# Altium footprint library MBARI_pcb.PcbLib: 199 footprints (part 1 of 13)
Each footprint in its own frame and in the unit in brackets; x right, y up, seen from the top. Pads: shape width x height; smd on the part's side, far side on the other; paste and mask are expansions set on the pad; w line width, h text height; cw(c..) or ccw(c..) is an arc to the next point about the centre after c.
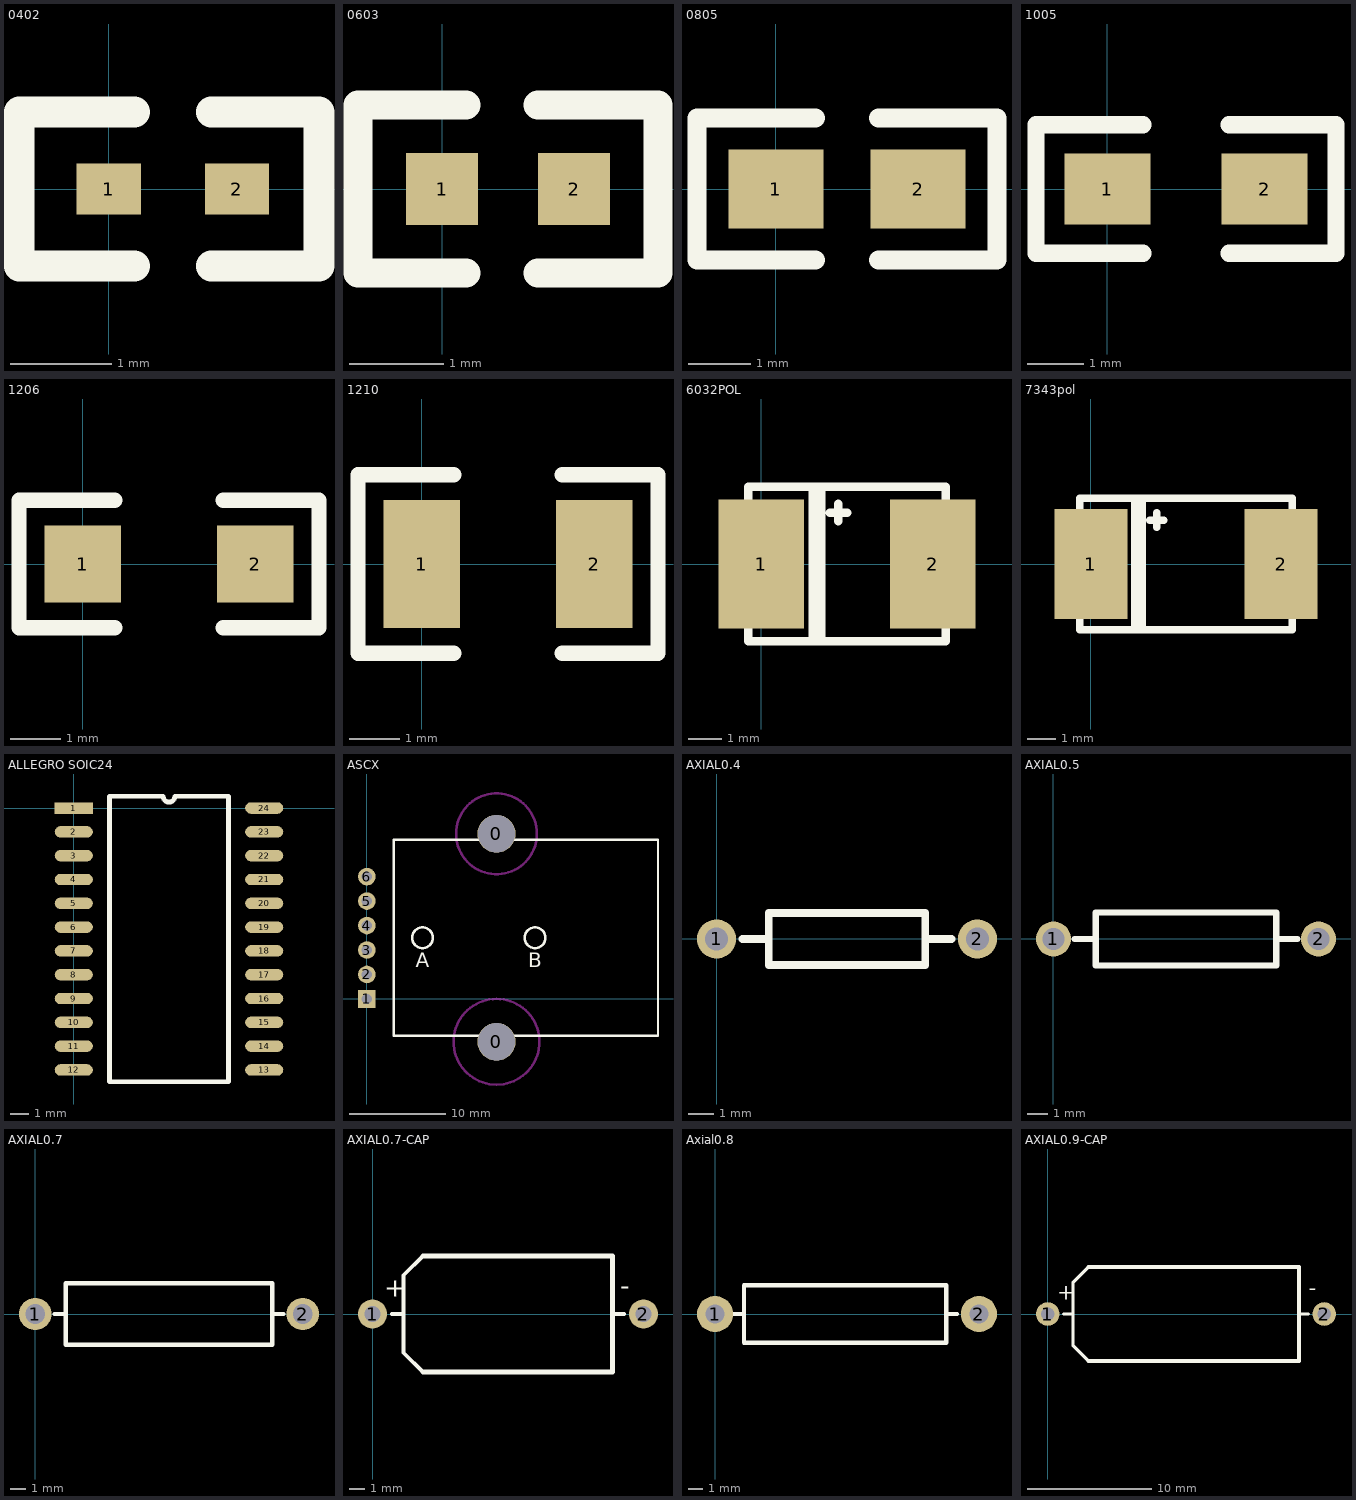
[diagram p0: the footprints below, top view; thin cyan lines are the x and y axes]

## 0402 [mil]
pads (2):
  rect 25x20 smd: 1(0,0) 2(50,0)
TopOverlay:
  lines w12: 10,-30 -35,-30 -35,30 10,30 ; 40,-30 82,-30 82,30 40,30

## 0603 [mil]
pads (2):
  rect 30x30 smd: 1(0,0) 2(55,0)
TopOverlay:
  lines w12: 10,-35 -35,-35 -35,35 10,35 ; 40,-35 90,-35 90,35 40,35

## 0805 [mil]
pads (2):
  rect 60x50 smd: 1(0,0) 2(90,0)
TopOverlay:
  lines w12: 25,-45 -50,-45 -50,45 25,45 ; 65,-45 140,-45 140,45 65,45

## 1005 [mil]
pads (2):
  rect 60x50 smd: 1(0,0) 2(110,0)
TopOverlay:
  lines w12: 25,-45 -50,-45 -50,45 25,45 ; 85,-45 160,-45 160,45 85,45

## 1206 [mil]
pads (2):
  rect 60x60 smd: 1(0,0) 2(135,0)
TopOverlay:
  lines w12: 25,-50 -50,-50 -50,50 25,50 ; 110,-50 185,-50 185,50 110,50

## 1210 [mil]
pads (2):
  rect 60x100 smd: 1(0,0) 2(135,0)
TopOverlay:
  lines w12: 25,-70 -50,-70 -50,70 25,70 ; 110,-70 185,-70 185,70 110,70

## 6032POL [mil]
pads (2):
  rect 100x150 smd: 1(0,0) 2(200,0)
TopOverlay:
  lines w10: -15,-75 -15,-90 215,-90 215,-75 ; -15,75 -15,90 215,90 215,75 ; 60,-90 60,90 ; 70,-90 70,90 ; 80,60 100,60 ; 90,50 90,70

## 7343pol [mil]
pads (2):
  rect 100x150 smd: 1(0,0) 2(260,0)
TopOverlay:
  lines w10: -15,-75 -15,-90 275,-90 275,-75 ; -15,75 -15,90 275,90 275,75 ; 60,-90 60,90 ; 70,-90 70,90 ; 80,60 100,60 ; 90,50 90,70

## ALLEGRO SOIC24 [mil]
pads (24):
  rect 80x24 smd: 1(0,0)
  oval 80x24 smd: 2(0,-50) 3(0,-100) 4(0,-150) 5(0,-200) 6(0,-250) 7(0,-300) 8(0,-350) 9(0,-400) 10(0,-450) 11(0,-500) 12(0,-550) 13(400,-550) 14(400,-500) 15(400,-450) 16(400,-400) 17(400,-350) 18(400,-300) 19(400,-250) 20(400,-200) 21(400,-150) 22(400,-100) 23(400,-50) 24(400,0)
TopOverlay:
  lines w10: 75,-575 75,25 187.5,25 ccw(c200,25) 212.5,25 325,25 325,-575 75,-575

## ASCX [mil]
pads (8):
  round 155 hole 152: 0(530,-175) 0(530,675)
  rect 72x72 hole 42: 1(0,0)
  round 72 hole 42: 2(0,100) 3(0,200) 4(0,300) 5(0,400) 6(0,500)
TopOverlay:
  circle w10: c227.57,250 r42.43
  circle w10: c687.57,250 r42.43
  lines w10: 110,-150 110,650 1190,650 1190,-150 110,-150
  text "A" at 200,130 h60
  text "B" at 660,130 h60
KeepOutLayer:
  circle w10: c530,675 r165.3
  circle w10: c530,-175 r175.29

## AXIAL0.4 [mil]
pads (2):
  round 60 hole 35: 1(0,0) 2(400,0)
TopOverlay:
  lines w12: 40,-0.04 80,-0.04 ; 320,-0.04 360,-0.04 ; 80,-40.04 320,-40.04 320,39.96 80,39.96 80,-40.04

## AXIAL0.5 [mil]
pads (2):
  round 66 hole 42: 1(0,0) 2(500,0)
TopOverlay:
  lines w12: 40,-0.04 80,-0.04 ; 420,-0.04 460,-0.04 ; 80,-50.04 80,49.96 420,49.96 420,-50.04 80,-50.04

## AXIAL0.7 [mil]
pads (2):
  round 85 hole 52: 1(0,0) 2(700,0)
TopOverlay:
  lines w10: 50,0 80,0 ; 620,0 650,0
  lines w12: 80,-80 620,-80 620,80 80,80 80,-80

## AXIAL0.7-CAP [mil]
pads (2):
  round 75 hole 42: 1(0,0) 2(700,0)
TopOverlay:
  lines w10: 50,0 80,0 ; 130,-150 80,-100 80,0 ; 130,150 80,100 80,0 ; 620,0 650,0
  lines w12: 130,-150 620,-150 620,150 130,150
  text "+" at 30,45 h50
  text "-" at 640,50 h50

## Axial0.8 [mil]
pads (2):
  round 100 hole 52: 1(0,0) 2(730,0)
TopOverlay:
  lines w10: 50,0 80,0 ; 640,0 670,0
  lines w12: 80,-80 640,-80 640,80 80,80 80,-80

## AXIAL0.9-CAP [mil]
pads (2):
  round 75 hole 42: 1(0,0) 2(880,0)
TopOverlay:
  lines w10: 50,0 80,0 ; 130,-150 80,-100 80,0 ; 130,150 80,100 80,0 ; 800,0 830,0
  lines w12: 130,-150 800,-150 800,150 130,150
  text "-" at 830,60 h50
  text "+" at 30,45 h50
